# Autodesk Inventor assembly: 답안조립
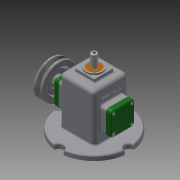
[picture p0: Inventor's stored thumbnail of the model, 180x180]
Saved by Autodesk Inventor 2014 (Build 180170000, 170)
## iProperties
Created: 2018-07
Part Number: 답안조립
Document SubType Name: Assembly
Designer: kh
Author: kh
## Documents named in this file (16)
- C:\Users\kh\Desktop\480707V1012\답안조립.iam
- C:\Users\kh\Desktop\480707V1012\본체.ipt
- C:\Users\kh\Desktop\480707V1012\링크.ipt
- C:\Users\kh\Desktop\480707V1012\멈춤나사 M3x8.ipt
- C:\Users\kh\Desktop\480707V1012\베어링 12x32x10.ipt
- C:\Users\kh\Desktop\480707V1012\볼트 M4.ipt
- C:\Users\kh\Desktop\480707V1012\부시.ipt
- C:\Users\kh\Desktop\480707V1012\슬라이드.ipt
- C:\Users\kh\Desktop\480707V1012\앞커버.ipt
- C:\Users\kh\Desktop\480707V1012\오일 실 12 25 7.ipt
- C:\Users\kh\Desktop\480707V1012\키 4x4x10.ipt
- C:\Users\kh\Desktop\480707V1012\편심축.ipt
- C:\Users\kh\Desktop\480707V1012\핀 5x18.ipt
- C:\Users\kh\Desktop\480707V1012\V벨트풀리.ipt
- C:\Users\kh\Desktop\480707V1012\고정핀 1.2x8.ipt
- C:\Users\kh\Desktop\480707V1012\뒤커버.ipt
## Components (3 placed, 3 different names)
1. 핀 5x18:1 — Insert:6, Mate:2, Flush:1
2. V벨트풀리:1 — Insert:9, Mate:3, Mate:4
3. 고정핀 1.2x8:1 — Mate:2, Angle:2, Flush:1
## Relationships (7: Mate 3, Insert 2, Angle 1, Flush 1)
- Insert:6: 핀 5x18:1
- Mate:2: 핀 5x18:1 ↔ 고정핀 1.2x8:1
- Insert:9: V벨트풀리:1
- Mate:3: V벨트풀리:1
- Angle:2: 고정핀 1.2x8:1
- Flush:1: 핀 5x18:1 ↔ 고정핀 1.2x8:1
- Mate:4: V벨트풀리:1
